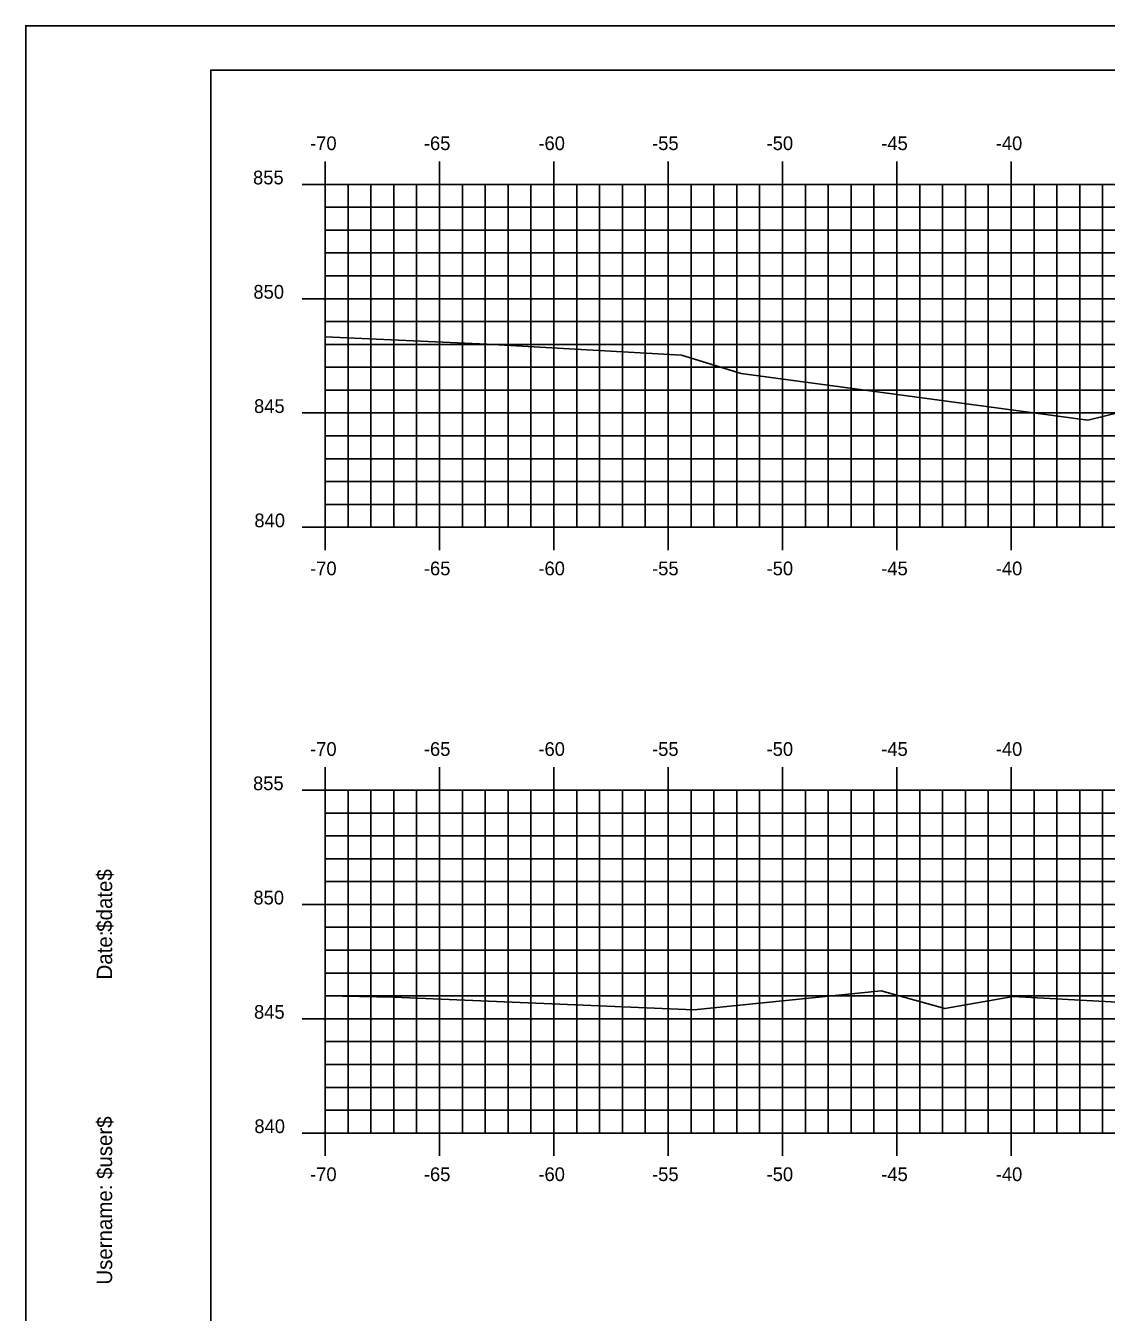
# Model space of a CAD drawing. Extents: x 2194256 to 2194747, y 863888 to 863998.
# Drawn here: x 2194393.6 to 2194440.9, y 863942.1 to 863998.4 of the extents above; entities that cross this region are included whole.
import ezdxf

# ---------------------------------------------------------------- set-up
doc = ezdxf.new("R2010")
doc.units = 0
for name, color, linetype in [('BORDER', 7, 'Continuous'), ('H_V ANNOTATION', 7, 'Continuous'), ('MAJOR', 7, 'Continuous'), ('MINOR', 7, 'Continuous'), ('PLOT BOUNDARY', 7, 'Continuous'), ('S_Roadway_Centerline', 7, 'Continuous')]:
    doc.layers.add(name, color=color, linetype=linetype)

msp = doc.modelspace()

# ---------------------------------------------------------------- linework, layer by layer
at = {"layer": 'BORDER'}
msp.add_lwpolyline([(2194401.743, 863891.446), (2194561.743, 863891.446), (2194561.743, 863996.446), (2194401.743, 863996.446)], close=True, dxfattribs=at)
at = {"layer": 'MAJOR'}
for p, q in [((2194406.743, 863992.448), (2194406.743, 863991.446)), ((2194411.743, 863992.448), (2194411.743, 863991.446)), ((2194416.743, 863992.448), (2194416.743, 863991.446)), ((2194421.743, 863992.448), (2194421.743, 863991.446)), ((2194426.743, 863992.448), (2194426.743, 863991.446)), ((2194431.743, 863992.448), (2194431.743, 863991.446)), ((2194436.743, 863992.448), (2194436.743, 863991.446)), ((2194405.741, 863991.446), (2194406.743, 863991.446)), ((2194406.743, 863991.446), (2194546.743, 863991.446)), ((2194406.743, 863976.446), (2194406.743, 863991.446)), ((2194406.743, 863976.446), (2194406.743, 863991.446)), ((2194411.743, 863976.446), (2194411.743, 863991.446)), ((2194416.743, 863976.446), (2194416.743, 863991.446)), ((2194421.743, 863976.446), (2194421.743, 863991.446)), ((2194426.743, 863976.446), (2194426.743, 863991.446)), ((2194431.743, 863976.446), (2194431.743, 863991.446)), ((2194436.743, 863976.446), (2194436.743, 863991.446)), ((2194405.741, 863986.446), (2194406.743, 863986.446)), ((2194406.743, 863986.446), (2194546.743, 863986.446)), ((2194405.741, 863981.446), (2194406.743, 863981.446)), ((2194406.743, 863981.446), (2194546.743, 863981.446)), ((2194405.741, 863976.446), (2194406.743, 863976.446)), ((2194406.743, 863976.446), (2194546.743, 863976.446)), ((2194406.743, 863975.444), (2194406.743, 863976.446)), ((2194411.743, 863975.444), (2194411.743, 863976.446)), ((2194416.743, 863975.444), (2194416.743, 863976.446)), ((2194421.743, 863975.444), (2194421.743, 863976.446)), ((2194426.743, 863975.444), (2194426.743, 863976.446)), ((2194431.743, 863975.444), (2194431.743, 863976.446)), ((2194436.743, 863975.444), (2194436.743, 863976.446)), ((2194406.743, 863965.948), (2194406.743, 863964.946)), ((2194411.743, 863965.948), (2194411.743, 863964.946)), ((2194416.743, 863965.948), (2194416.743, 863964.946)), ((2194421.743, 863965.948), (2194421.743, 863964.946)), ((2194426.743, 863965.948), (2194426.743, 863964.946)), ((2194431.743, 863965.948), (2194431.743, 863964.946)), ((2194436.743, 863965.948), (2194436.743, 863964.946)), ((2194405.741, 863964.946), (2194406.743, 863964.946)), ((2194406.743, 863964.946), (2194546.743, 863964.946)), ((2194406.743, 863964.946), (2194546.743, 863964.946)), ((2194406.743, 863949.946), (2194406.743, 863964.946)), ((2194406.743, 863949.946), (2194406.743, 863964.946)), ((2194411.743, 863949.946), (2194411.743, 863964.946)), ((2194416.743, 863949.946), (2194416.743, 863964.946)), ((2194421.743, 863949.946), (2194421.743, 863964.946)), ((2194426.743, 863949.946), (2194426.743, 863964.946)), ((2194431.743, 863949.946), (2194431.743, 863964.946)), ((2194436.743, 863949.946), (2194436.743, 863964.946)), ((2194405.741, 863959.946), (2194406.743, 863959.946)), ((2194406.743, 863959.946), (2194546.743, 863959.946)), ((2194405.741, 863954.946), (2194406.743, 863954.946)), ((2194406.743, 863954.946), (2194546.743, 863954.946)), ((2194405.741, 863949.946), (2194406.743, 863949.946)), ((2194406.743, 863949.946), (2194546.743, 863949.946)), ((2194406.743, 863948.944), (2194406.743, 863949.946)), ((2194411.743, 863948.944), (2194411.743, 863949.946)), ((2194416.743, 863948.944), (2194416.743, 863949.946)), ((2194421.743, 863948.944), (2194421.743, 863949.946)), ((2194426.743, 863948.944), (2194426.743, 863949.946)), ((2194431.743, 863948.944), (2194431.743, 863949.946)), ((2194436.743, 863948.944), (2194436.743, 863949.946))]:
    msp.add_line(p, q, dxfattribs=at)
at = {"layer": 'MINOR'}
for p, q in [((2194407.743, 863976.446), (2194407.743, 863991.446)), ((2194408.743, 863976.446), (2194408.743, 863991.446)), ((2194409.743, 863976.446), (2194409.743, 863991.446)), ((2194410.743, 863976.446), (2194410.743, 863991.446)), ((2194412.743, 863976.446), (2194412.743, 863991.446)), ((2194413.743, 863976.446), (2194413.743, 863991.446)), ((2194414.743, 863976.446), (2194414.743, 863991.446)), ((2194415.743, 863976.446), (2194415.743, 863991.446)), ((2194417.743, 863976.446), (2194417.743, 863991.446)), ((2194418.743, 863976.446), (2194418.743, 863991.446)), ((2194419.743, 863976.446), (2194419.743, 863991.446)), ((2194420.743, 863976.446), (2194420.743, 863991.446)), ((2194422.743, 863976.446), (2194422.743, 863991.446)), ((2194423.743, 863976.446), (2194423.743, 863991.446)), ((2194424.743, 863976.446), (2194424.743, 863991.446)), ((2194425.743, 863976.446), (2194425.743, 863991.446)), ((2194427.743, 863976.446), (2194427.743, 863991.446)), ((2194428.743, 863976.446), (2194428.743, 863991.446)), ((2194429.743, 863976.446), (2194429.743, 863991.446)), ((2194430.743, 863976.446), (2194430.743, 863991.446)), ((2194432.743, 863976.446), (2194432.743, 863991.446)), ((2194433.743, 863976.446), (2194433.743, 863991.446)), ((2194434.743, 863976.446), (2194434.743, 863991.446)), ((2194435.743, 863976.446), (2194435.743, 863991.446)), ((2194437.743, 863976.446), (2194437.743, 863991.446)), ((2194438.743, 863976.446), (2194438.743, 863991.446)), ((2194439.743, 863976.446), (2194439.743, 863991.446)), ((2194440.743, 863976.446), (2194440.743, 863991.446)), ((2194406.743, 863990.446), (2194546.743, 863990.446)), ((2194406.743, 863990.446), (2194407.745, 863990.446)), ((2194406.743, 863989.446), (2194546.743, 863989.446)), ((2194406.743, 863989.446), (2194407.745, 863989.446)), ((2194406.743, 863988.446), (2194546.743, 863988.446)), ((2194406.743, 863988.446), (2194407.745, 863988.446)), ((2194406.743, 863987.446), (2194546.743, 863987.446)), ((2194406.743, 863987.446), (2194407.745, 863987.446)), ((2194406.743, 863985.446), (2194546.743, 863985.446)), ((2194406.743, 863985.446), (2194407.745, 863985.446)), ((2194406.743, 863984.446), (2194546.743, 863984.446)), ((2194406.743, 863984.446), (2194407.745, 863984.446)), ((2194406.743, 863983.446), (2194546.743, 863983.446)), ((2194406.743, 863983.446), (2194407.745, 863983.446)), ((2194406.743, 863982.446), (2194546.743, 863982.446)), ((2194406.743, 863982.446), (2194407.745, 863982.446)), ((2194406.743, 863980.446), (2194546.743, 863980.446)), ((2194406.743, 863980.446), (2194407.745, 863980.446)), ((2194406.743, 863979.446), (2194546.743, 863979.446)), ((2194406.743, 863979.446), (2194407.745, 863979.446)), ((2194406.743, 863978.446), (2194546.743, 863978.446)), ((2194406.743, 863978.446), (2194407.745, 863978.446)), ((2194406.743, 863977.446), (2194546.743, 863977.446)), ((2194406.743, 863977.446), (2194407.745, 863977.446)), ((2194407.743, 863949.946), (2194407.743, 863964.946)), ((2194408.743, 863949.946), (2194408.743, 863964.946)), ((2194409.743, 863949.946), (2194409.743, 863964.946)), ((2194410.743, 863949.946), (2194410.743, 863964.946)), ((2194412.743, 863949.946), (2194412.743, 863964.946)), ((2194413.743, 863949.946), (2194413.743, 863964.946)), ((2194414.743, 863949.946), (2194414.743, 863964.946)), ((2194415.743, 863949.946), (2194415.743, 863964.946)), ((2194417.743, 863949.946), (2194417.743, 863964.946)), ((2194418.743, 863949.946), (2194418.743, 863964.946)), ((2194419.743, 863949.946), (2194419.743, 863964.946)), ((2194420.743, 863949.946), (2194420.743, 863964.946)), ((2194422.743, 863949.946), (2194422.743, 863964.946)), ((2194423.743, 863949.946), (2194423.743, 863964.946)), ((2194424.743, 863949.946), (2194424.743, 863964.946)), ((2194425.743, 863949.946), (2194425.743, 863964.946)), ((2194427.743, 863949.946), (2194427.743, 863964.946)), ((2194428.743, 863949.946), (2194428.743, 863964.946)), ((2194429.743, 863949.946), (2194429.743, 863964.946)), ((2194430.743, 863949.946), (2194430.743, 863964.946)), ((2194432.743, 863949.946), (2194432.743, 863964.946)), ((2194433.743, 863949.946), (2194433.743, 863964.946)), ((2194434.743, 863949.946), (2194434.743, 863964.946)), ((2194435.743, 863949.946), (2194435.743, 863964.946)), ((2194437.743, 863949.946), (2194437.743, 863964.946)), ((2194438.743, 863949.946), (2194438.743, 863964.946)), ((2194439.743, 863949.946), (2194439.743, 863964.946)), ((2194440.743, 863949.946), (2194440.743, 863964.946)), ((2194406.743, 863963.946), (2194546.743, 863963.946)), ((2194406.743, 863963.946), (2194407.745, 863963.946)), ((2194406.743, 863962.946), (2194546.743, 863962.946)), ((2194406.743, 863962.946), (2194407.745, 863962.946)), ((2194406.743, 863961.946), (2194546.743, 863961.946)), ((2194406.743, 863961.946), (2194407.745, 863961.946)), ((2194406.743, 863960.946), (2194546.743, 863960.946)), ((2194406.743, 863960.946), (2194407.745, 863960.946)), ((2194406.743, 863958.946), (2194546.743, 863958.946)), ((2194406.743, 863958.946), (2194407.745, 863958.946)), ((2194406.743, 863957.946), (2194546.743, 863957.946)), ((2194406.743, 863957.946), (2194407.745, 863957.946)), ((2194406.743, 863956.946), (2194546.743, 863956.946)), ((2194406.743, 863956.946), (2194407.745, 863956.946)), ((2194406.743, 863955.946), (2194546.743, 863955.946)), ((2194406.743, 863955.946), (2194407.745, 863955.946)), ((2194406.743, 863953.946), (2194546.743, 863953.946)), ((2194406.743, 863953.946), (2194407.745, 863953.946)), ((2194406.743, 863952.946), (2194546.743, 863952.946)), ((2194406.743, 863952.946), (2194407.745, 863952.946)), ((2194406.743, 863951.946), (2194546.743, 863951.946)), ((2194406.743, 863951.946), (2194407.745, 863951.946)), ((2194406.743, 863950.946), (2194546.743, 863950.946)), ((2194406.743, 863950.946), (2194407.745, 863950.946))]:
    msp.add_line(p, q, dxfattribs=at)
at = {"layer": 'PLOT BOUNDARY'}
msp.add_lwpolyline([(2194393.65, 863888.387), (2194563.65, 863888.387), (2194563.65, 863998.387), (2194393.65, 863998.387)], close=True, dxfattribs=at)
at = {"layer": 'S_Roadway_Centerline'}
for points in [[(2194406.743, 863984.776), (2194413.814, 863984.462), (2194422.331, 863983.975), (2194424.939, 863983.173), (2194440.092, 863981.136), (2194445.1, 863982.351), (2194450.863, 863983.373), (2194461.063, 863986.367), (2194463.856, 863986.522), (2194465.566, 863986.66), (2194471.54, 863986.672), (2194476.678, 863986.745), (2194482.483, 863986.609), (2194488.569, 863986.453), (2194490.962, 863986.285), (2194492.004, 863986.208), (2194497.241, 863986.134), (2194498.885, 863986.051), (2194505.695, 863985.992)], [(2194406.743, 863955.952), (2194409.745, 863955.89), (2194422.859, 863955.341), (2194431.054, 863956.173), (2194433.839, 863955.397), (2194436.828, 863955.919), (2194441.916, 863955.643)]]:
    msp.add_lwpolyline(points, dxfattribs=at)

# ---------------------------------------------------------------- texts
at = {"layer": 'BORDER'}
for s, p in [('$date$', (2194397.428, 863958.751)), ('Date:', (2194397.428, 863956.663)), ('$user$', (2194397.428, 863947.937)), ('Username:', (2194397.428, 863943.314))]:
    msp.add_text(s, height=0.6696, rotation=90, dxfattribs=at).set_placement(p)
at = {"layer": 'H_V ANNOTATION'}
for s, p in [('-70', (2194406.084, 863992.946)), ('-65', (2194411.06, 863992.946)), ('-60', (2194416.068, 863992.946)), ('-55', (2194421.039, 863992.946)), ('-50', (2194426.047, 863992.946)), ('-45', (2194431.06, 863992.946)), ('-40', (2194436.068, 863992.946)), ('855', (2194403.589, 863991.446)), ('850', (2194403.605, 863986.446)), ('845', (2194403.632, 863981.446)), ('840', (2194403.648, 863976.446)), ('-70', (2194406.084, 863974.346)), ('-65', (2194411.06, 863974.346)), ('-60', (2194416.068, 863974.346)), ('-55', (2194421.039, 863974.346)), ('-50', (2194426.047, 863974.346)), ('-45', (2194431.06, 863974.346)), ('-40', (2194436.068, 863974.346)), ('-70', (2194406.084, 863966.446)), ('-65', (2194411.06, 863966.446)), ('-60', (2194416.068, 863966.446)), ('-55', (2194421.039, 863966.446)), ('-50', (2194426.047, 863966.446)), ('-45', (2194431.06, 863966.446)), ('-40', (2194436.068, 863966.446)), ('855', (2194403.589, 863964.946)), ('850', (2194403.605, 863959.946)), ('845', (2194403.632, 863954.946)), ('840', (2194403.648, 863949.946)), ('-70', (2194406.084, 863947.846)), ('-65', (2194411.06, 863947.846)), ('-60', (2194416.068, 863947.846)), ('-55', (2194421.039, 863947.846)), ('-50', (2194426.047, 863947.846)), ('-45', (2194431.06, 863947.846)), ('-40', (2194436.068, 863947.846))]:
    msp.add_text(s, height=0.6, dxfattribs=at).set_placement(p)

doc.saveas('drawing.dxf')
